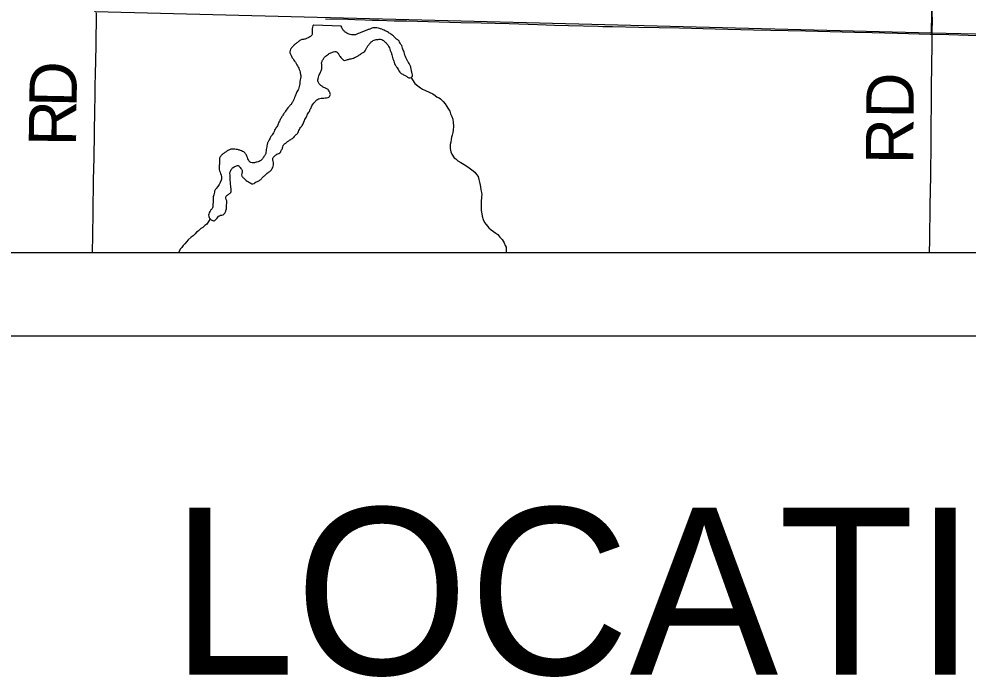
# Model space of a CAD drawing. Extents: x 0 to 34, y 0 to 22.
# Drawn here: x 4.244 to 5.383, y 13.591 to 14.38 of the extents above; entities that cross this region are included whole.
import ezdxf

# ---------------------------------------------------------------- set-up
doc = ezdxf.new("R2010")
doc.units = 0
for name, color, linetype in [('GM_X_County_Road', 7, 'Continuous'), ('GM_X_County_Road_Text', 7, 'Continuous'), ('GM_X_Minor_Lake', 7, 'Continuous'), ('GM_X_Minor_River', 7, 'Continuous'), ('GM_X_Section', 7, 'Continuous'), ('GM_X_Township_Road', 7, 'Continuous'), ('SH_Data', 7, 'Continuous'), ('SH_Text', 7, 'Continuous')]:
    doc.layers.add(name, color=color, linetype=linetype)

msp = doc.modelspace()

# ---------------------------------------------------------------- linework, layer by layer
at = {"layer": 'GM_X_County_Road'}
for points in [[(4.3325, 14.1), (4.3329, 14.1206), (4.3333, 14.1479), (4.3338, 14.1871), (4.3344, 14.2131), (4.3353, 14.2716), (4.3356, 14.2853), (4.3358, 14.3002), (4.3361, 14.3132), (4.3369, 14.3474), (4.3375, 14.3873)], [(5.34, 14.3615), (5.3402, 14.3819)], [(5.3367, 14.1), (5.3369, 14.1147), (5.3376, 14.1563), (5.3381, 14.1917), (5.3386, 14.2315), (5.3392, 14.298), (5.3399, 14.3496), (5.34, 14.3615)]]:
    msp.add_lwpolyline(points, dxfattribs=at)
at = {"layer": 'GM_X_Minor_Lake'}
msp.add_line((4.6309, 14.3712), (4.5981, 14.3725), dxfattribs=at)
for points in [[(4.5981, 14.3725), (4.598, 14.3725), (4.5964, 14.3699), (4.5959, 14.3664), (4.5962, 14.363), (4.595, 14.3596), (4.5911, 14.3571), (4.5876, 14.3556), (4.5838, 14.355), (4.5803, 14.3532), (4.5776, 14.351), (4.5749, 14.3491), (4.5726, 14.3465), (4.5702, 14.3436), (4.5693, 14.3402), (4.5704, 14.3367), (4.5722, 14.3333), (4.5759, 14.3278), (4.5777, 14.3247), (4.5806, 14.3193), (4.5816, 14.3159), (4.5823, 14.3121), (4.5822, 14.3083), (4.5813, 14.3049), (4.5813, 14.3022), (4.5804, 14.2988), (4.5796, 14.2958), (4.5772, 14.2913), (4.5756, 14.2872), (4.5743, 14.2842), (4.5727, 14.2808), (4.5707, 14.2774), (4.568, 14.2745), (4.5641, 14.2692), (4.5621, 14.2663), (4.5597, 14.2629), (4.5577, 14.2591), (4.5557, 14.255), (4.5537, 14.2505), (4.5509, 14.2464), (4.5497, 14.2434), (4.5481, 14.2408), (4.5461, 14.2382), (4.5441, 14.234), (4.5425, 14.2311), (4.5417, 14.2277), (4.5412, 14.225), (4.5407, 14.2216), (4.5403, 14.2186), (4.5387, 14.2156), (4.5363, 14.2122), (4.5324, 14.2089), (4.5297, 14.2082), (4.5259, 14.2072)], [(4.5974, 14.2782), (4.5997, 14.2808), (4.6025, 14.2834), (4.6051, 14.2845), (4.6086, 14.2848), (4.6116, 14.2851), (4.6151, 14.2857), (4.6178, 14.2883), (4.6171, 14.2918), (4.6157, 14.2945), (4.6127, 14.2964), (4.6101, 14.2977), (4.6071, 14.2996), (4.6045, 14.302), (4.603, 14.3054), (4.6031, 14.3081), (4.604, 14.3115), (4.6052, 14.3141), (4.6068, 14.3175), (4.6076, 14.3201), (4.6077, 14.3236), (4.6074, 14.327), (4.6086, 14.3304), (4.6106, 14.3337), (4.6134, 14.3359), (4.6176, 14.3389), (4.6215, 14.3403), (4.6245, 14.3406), (4.6271, 14.3386), (4.6289, 14.3355), (4.6319, 14.332), (4.6345, 14.3301), (4.6376, 14.3307), (4.6414, 14.3318), (4.6441, 14.3325), (4.6495, 14.3346), (4.6529, 14.3368), (4.6556, 14.3386), (4.6587, 14.3404), (4.6603, 14.3431), (4.6619, 14.3461), (4.6639, 14.3487), (4.6663, 14.3516), (4.669, 14.3538), (4.6717, 14.3549), (4.6743, 14.3552), (4.6781, 14.3555), (4.6808, 14.3543), (4.6834, 14.3523), (4.686, 14.3496), (4.6882, 14.3465), (4.6903, 14.3404), (4.6917, 14.3369), (4.6924, 14.3335), (4.6935, 14.3304), (4.6945, 14.3277), (4.6956, 14.3246), (4.6978, 14.3215), (4.7029, 14.3145), (4.7067, 14.3125), (4.7097, 14.3106), (4.7127, 14.309), (4.7162, 14.3112), (4.7159, 14.3142), (4.7152, 14.318), (4.7145, 14.3215), (4.7131, 14.3249), (4.7116, 14.3276), (4.7098, 14.3303), (4.7084, 14.3334), (4.7073, 14.3365), (4.7063, 14.3399), (4.7045, 14.3449), (4.7034, 14.348), (4.7016, 14.3507), (4.7002, 14.3534), (4.6972, 14.3557), (4.6942, 14.3589), (4.6916, 14.3608), (4.6875, 14.3636), (4.6837, 14.3656), (4.6811, 14.3668), (4.6781, 14.368), (4.6755, 14.3689), (4.672, 14.369), (4.669, 14.369), (4.6659, 14.368), (4.6625, 14.3666), (4.6586, 14.3651), (4.6544, 14.3634), (4.6513, 14.3623), (4.6479, 14.3609), (4.6418, 14.361), (4.6365, 14.3635), (4.6339, 14.3658), (4.6321, 14.3685), (4.6309, 14.3712)], [(4.5259, 14.2072), (4.5225, 14.2076), (4.5195, 14.2108), (4.5185, 14.2135), (4.5167, 14.2173), (4.5141, 14.2204), (4.5111, 14.2216), (4.5077, 14.2229), (4.505, 14.2233), (4.5016, 14.2238), (4.4955, 14.2224), (4.4928, 14.2206), (4.4897, 14.2184), (4.487, 14.2162), (4.485, 14.2128), (4.4848, 14.2056), (4.4843, 14.203), (4.4846, 14.1995), (4.4867, 14.1926), (4.4874, 14.1892), (4.4869, 14.1866), (4.481, 14.1765), (4.479, 14.1735), (4.4785, 14.1704), (4.4777, 14.1678), (4.4772, 14.1633), (4.477, 14.156), (4.4766, 14.1534), (4.4746, 14.1508), (4.4726, 14.1474), (4.4718, 14.1444), (4.4724, 14.1417), (4.475, 14.139), (4.4784, 14.1378), (4.4819, 14.1411), (4.4862, 14.1444), (4.4893, 14.1451), (4.4916, 14.1477), (4.4928, 14.151), (4.4933, 14.1537), (4.4934, 14.1571), (4.4938, 14.1598), (4.4925, 14.1666), (4.4952, 14.1692), (4.4983, 14.1718), (4.4988, 14.1745), (4.4982, 14.1813), (4.4979, 14.1844), (4.4976, 14.1878), (4.4977, 14.1912), (4.4974, 14.1946), (4.4983, 14.198), (4.4999, 14.2006), (4.5033, 14.2028), (4.5072, 14.2039), (4.5098, 14.2015), (4.512, 14.198), (4.5115, 14.1946), (4.5118, 14.1912), (4.5144, 14.1885), (4.517, 14.1861), (4.5196, 14.1845), (4.5249, 14.1821), (4.5276, 14.1836), (4.5303, 14.185), (4.5337, 14.1868), (4.5365, 14.1898), (4.5396, 14.1924), (4.5431, 14.1957), (4.5458, 14.1975), (4.5482, 14.2005), (4.5494, 14.2031), (4.5498, 14.2065), (4.5492, 14.2092), (4.5489, 14.213), (4.5512, 14.2156), (4.5547, 14.2182), (4.5574, 14.2193), (4.559, 14.2222), (4.5606, 14.2252), (4.5611, 14.2279), (4.5638, 14.2305), (4.5665, 14.2327), (4.5696, 14.2349), (4.5731, 14.2371), (4.5762, 14.2404), (4.579, 14.2434), (4.5814, 14.2486), (4.5841, 14.252), (4.5862, 14.2565), (4.5874, 14.2591), (4.589, 14.2617), (4.5906, 14.2655), (4.5922, 14.2681), (4.5938, 14.2715), (4.5958, 14.2756), (4.5974, 14.2782)]]:
    msp.add_spline(points, degree=3, dxfattribs=at)
at = {"layer": 'GM_X_Minor_River'}
for points in [[(4.7145, 14.3101), (4.7191, 14.3025), (4.7228, 14.2994), (4.7258, 14.2974), (4.7284, 14.2957), (4.7318, 14.2941), (4.7408, 14.29), (4.7434, 14.288), (4.746, 14.286), (4.7482, 14.2852), (4.7501, 14.284), (4.753, 14.2809), (4.7556, 14.2781), (4.7574, 14.275), (4.7589, 14.273), (4.7611, 14.2692), (4.7621, 14.2661), (4.7635, 14.263), (4.7646, 14.2595), (4.7652, 14.2557), (4.7654, 14.2511), (4.7653, 14.2466), (4.7648, 14.2436), (4.7639, 14.2405), (4.7631, 14.2379), (4.7626, 14.2353), (4.7622, 14.2322), (4.7617, 14.2292), (4.7615, 14.2243), (4.7625, 14.2204), (4.7636, 14.2177), (4.7665, 14.2131), (4.7684, 14.2119), (4.7706, 14.2095), (4.7743, 14.2075), (4.7784, 14.2051), (4.7829, 14.2023), (4.7874, 14.1991), (4.7911, 14.1963), (4.7933, 14.1935), (4.7951, 14.1908), (4.7961, 14.1874), (4.7971, 14.1824), (4.7981, 14.1785), (4.7984, 14.1751), (4.7991, 14.1717), (4.7994, 14.1694), (4.7993, 14.1671), (4.7987, 14.1603), (4.7986, 14.1584), (4.7986, 14.1557), (4.7988, 14.1526), (4.7988, 14.15), (4.7991, 14.1481), (4.7994, 14.1462), (4.8001, 14.1435), (4.8011, 14.1393), (4.8029, 14.1358), (4.8047, 14.1334), (4.808, 14.1295), (4.8106, 14.1271), (4.8136, 14.1251), (4.8165, 14.1228), (4.8188, 14.1212), (4.8213, 14.118), (4.8239, 14.1153), (4.825, 14.1134), (4.8265, 14.1114), (4.8275, 14.1083), (4.8286, 14.106), (4.8289, 14.1033), (4.8288, 14.1007), (4.8289, 14.1)], [(4.4738, 14.1403), (4.4696, 14.1338), (4.4672, 14.132), (4.4649, 14.1298), (4.4625, 14.1284), (4.4594, 14.1254), (4.4574, 14.124), (4.4555, 14.1221), (4.4531, 14.1199), (4.4508, 14.1181), (4.4473, 14.1148), (4.4453, 14.1126), (4.4433, 14.11), (4.4413, 14.1081), (4.4397, 14.1059), (4.4382, 14.1041), (4.4361, 14.1007), (4.4356, 14.1)]]:
    msp.add_lwpolyline(points, dxfattribs=at)
at = {"layer": 'GM_X_Section'}
for points in [[(5.3552, 15.367), (5.3389, 14.3627), (4.3359, 14.3884), (4.3576, 15.3927)], [(5.3552, 15.367), (6.3631, 15.3454), (6.3444, 14.34), (5.3389, 14.3627)]]:
    msp.add_lwpolyline(points, close=True, dxfattribs=at)
at = {"layer": 'GM_X_Township_Road'}
for points in [[(2.1, 18.4074), (2.1, 14.1), (7.3507, 14.1), (7.3542, 14.3107), (7.3767, 15.3155), (7.3854, 16.3696)], [(4.612, 14.3801), (4.6387, 14.3795), (4.6474, 14.3793), (4.6598, 14.3788), (4.6679, 14.3785), (4.6766, 14.3782), (4.6946, 14.3776), (4.7095, 14.3774), (4.7353, 14.3767), (4.7744, 14.3756), (4.7988, 14.3751), (4.8323, 14.3743), (4.8667, 14.3732), (4.8869, 14.3725), (4.9037, 14.372), (4.9391, 14.371), (4.9447, 14.3709), (4.9565, 14.3707), (4.9878, 14.37), (5.0367, 14.369), (5.0795, 14.368), (5.1255, 14.3669), (5.1877, 14.3654), (5.2467, 14.3639), (5.2679, 14.3634), (5.2983, 14.3627), (5.3375, 14.3616), (5.34, 14.3615)], [(5.34, 14.3615), (5.3598, 14.3611), (5.3828, 14.3604), (5.4605, 14.3583), (5.5152, 14.3569), (5.5948, 14.3549), (5.6408, 14.354), (5.7296, 14.3523), (5.7756, 14.3514), (5.8359, 14.3503), (5.8428, 14.3502)]]:
    msp.add_lwpolyline(points, dxfattribs=at)
at = {"layer": 'SH_Data'}
for p, q in [((2.1, 14.1), (8.9, 14.1)), ((2, 14), (9, 14))]:
    msp.add_line(p, q, dxfattribs=at)

# ---------------------------------------------------------------- texts
at = {"layer": 'GM_X_County_Road_Text'}
for s, height, rotation, p in [('D', 0.0568, 88.8597, (4.3133, 14.2736)), ('RD', 0.05682, 89.5063, (5.317, 14.2055)), ('R', 0.0568, 89.4399, (4.3128, 14.2271))]:
    msp.add_text(s, height=height, rotation=rotation, dxfattribs=at).set_placement(p)
at = {"layer": 'SH_Text'}
msp.add_text('LOCATION MAP', height=0.2, dxfattribs=at).set_placement((4.4269, 13.5938))

doc.saveas('drawing.dxf')
